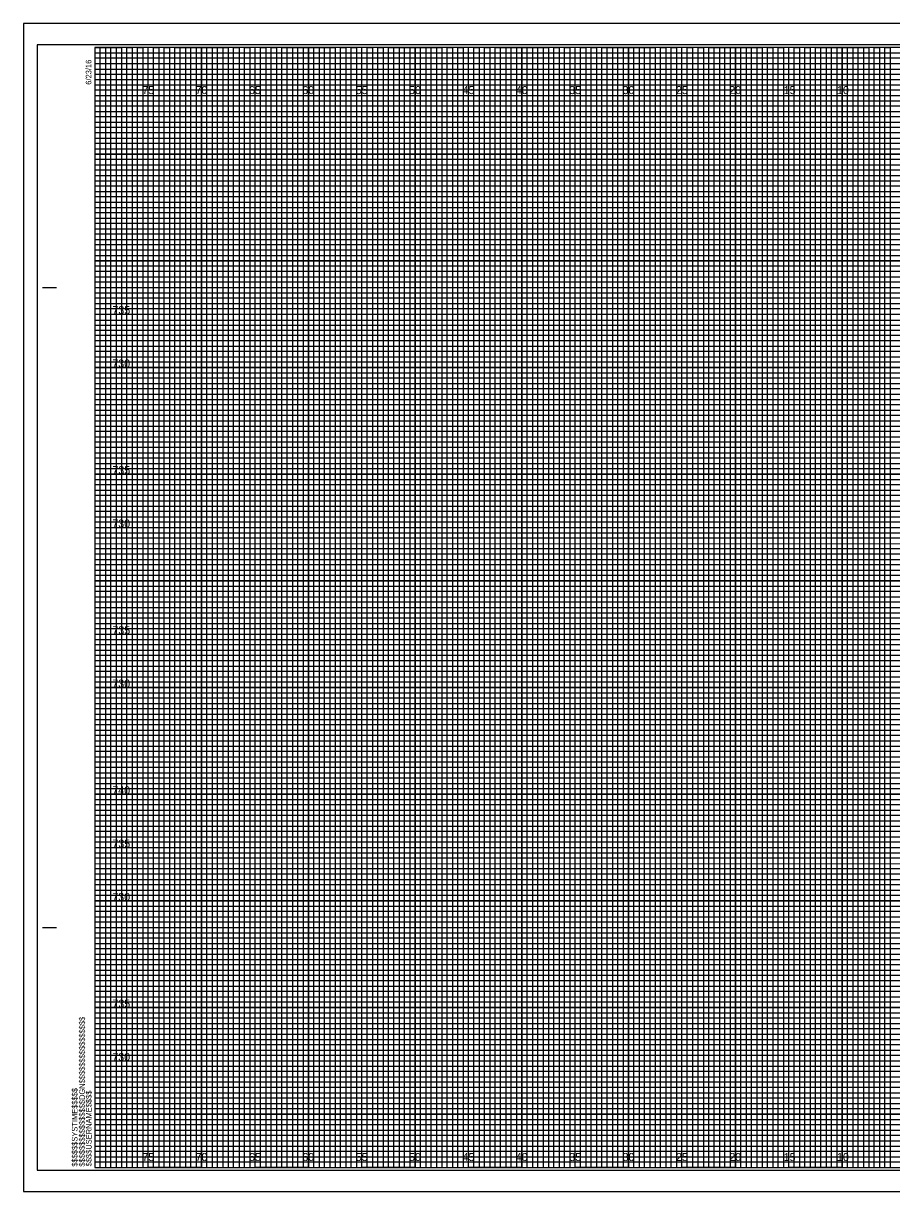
# Model space of a CAD drawing. Extents: x -7 to 162, y 108 to 217.
# Drawn here: x -6.7 to 74.6, y 107.7 to 217.2 of the extents above; entities that cross this region are included whole.
import ezdxf

# ---------------------------------------------------------------- set-up
doc = ezdxf.new("R2010")
doc.units = 0
for name, color, linetype in [('Exist Cross Section Cell', 7, 'Continuous'), ('Exist XS Center Line Elevation Label', 7, 'Continuous'), ('Exist XS Ground Line', 7, 'Continuous'), ('Prop CMT Pvmt Course 1', 7, 'Continuous'), ('Prop CMT Pvmt Course 2', 7, 'Continuous'), ('Prop CMT Pvmt Course 3', 7, 'Continuous'), ('Prop CMT Pvmt Surface', 7, 'Continuous'), ('Prop CMT Pvmt Surface Shoulder', 7, 'Continuous'), ('Prop CMT Shld Paved Course 1', 7, 'Continuous'), ('Prop CMT Shld Paved Course 2', 7, 'Continuous'), ('Prop CMT Shld Paved Course 3', 7, 'Continuous')]:
    doc.layers.add(name, color=color, linetype=linetype)

msp = doc.modelspace()

# ---------------------------------------------------------------- linework, layer by layer
at = {"layer": 'Exist XS Center Line Elevation Label'}
for points in [[(0, 215), (2.5, 215), (2.5, 110), (7.5, 110), (7.5, 215), (12.5, 215), (12.5, 110), (17.5, 110), (17.5, 215), (22.5, 215), (22.5, 110), (27.5, 110), (27.5, 215), (32.5, 215), (32.5, 110), (37.5, 110), (37.5, 215), (42.5, 215), (42.5, 110), (47.5, 110), (47.5, 215), (52.5, 215), (52.5, 110), (57.5, 110), (57.5, 215), (62.5, 215), (62.5, 110), (67.5, 110), (67.5, 215), (72.5, 215), (72.5, 110), (77.5, 110)], [(0, 212.5), (137.5, 212.5)], [(0, 202.5), (160, 202.5), (160, 207.5), (0, 207.5)], [(0, 192.5), (160, 192.5), (160, 197.5), (0, 197.5)], [(0, 182.5), (160, 182.5), (160, 187.5), (0, 187.5)], [(0, 172.5), (160, 172.5), (160, 177.5), (0, 177.5)], [(0, 162.5), (160, 162.5), (160, 167.5), (0, 167.5)], [(0, 152.5), (160, 152.5), (160, 157.5), (0, 157.5)], [(0, 142.5), (160, 142.5), (160, 147.5), (0, 147.5)], [(0, 132.5), (160, 132.5), (160, 137.5), (0, 137.5)], [(0, 122.5), (160, 122.5), (160, 127.5), (0, 127.5)], [(0, 112.5), (160, 112.5), (160, 117.5), (0, 117.5)]]:
    msp.add_lwpolyline(points, dxfattribs=at)
at = {"layer": 'Exist XS Ground Line'}
for p, q in [((5, 215), (0, 215)), ((5, 110), (5, 215)), ((15, 215), (10, 215)), ((10, 215), (10, 110)), ((15, 110), (15, 215)), ((25, 215), (20, 215)), ((20, 215), (20, 110)), ((25, 110), (25, 215)), ((35, 215), (30, 215)), ((30, 215), (30, 110)), ((35, 110), (35, 215)), ((45, 215), (40, 215)), ((40, 215), (40, 110)), ((45, 110), (45, 215)), ((55, 215), (50, 215)), ((50, 215), (50, 110)), ((55, 110), (55, 215)), ((65, 215), (60, 215)), ((60, 215), (60, 110)), ((65, 110), (65, 215)), ((75, 215), (70, 215)), ((70, 215), (70, 110)), ((10, 110), (5, 110)), ((20, 110), (15, 110)), ((30, 110), (25, 110)), ((40, 110), (35, 110)), ((50, 110), (45, 110)), ((60, 110), (55, 110)), ((70, 110), (65, 110))]:
    msp.add_line(p, q, dxfattribs=at)
for points in [[(0, 210), (160, 210), (160, 205), (0, 205)], [(0, 200), (160, 200), (160, 195), (0, 195)], [(0, 190), (160, 190), (160, 185), (0, 185)], [(0, 180), (160, 180), (160, 175), (0, 175)], [(0, 170), (160, 170), (160, 165), (0, 165)], [(0, 160), (160, 160), (160, 155), (0, 155)], [(0, 150), (160, 150), (160, 145), (0, 145)], [(0, 140), (160, 140), (160, 135), (0, 135)], [(0, 130), (160, 130), (160, 125), (0, 125)], [(0, 120), (160, 120), (160, 115), (0, 115)]]:
    msp.add_lwpolyline(points, dxfattribs=at)
at = {"layer": 'Prop CMT Pvmt Course 1'}
for p, q in [((5, 110), (5, 215)), ((10, 110), (10, 215)), ((15, 110), (15, 215)), ((20, 110), (20, 215)), ((25, 110), (25, 215)), ((30, 110), (30, 215)), ((35, 110), (35, 215)), ((40, 110), (40, 215)), ((45, 110), (45, 215)), ((50, 110), (50, 215)), ((55, 110), (55, 215)), ((60, 110), (60, 215)), ((65, 110), (65, 215)), ((70, 110), (70, 215)), ((0, 210), (160, 210)), ((0, 205), (160, 205)), ((0, 200), (160, 200)), ((0, 195), (160, 195)), ((0, 190), (160, 190)), ((0, 185), (160, 185)), ((0, 180), (160, 180)), ((0, 175), (160, 175)), ((0, 170), (160, 170)), ((0, 165), (160, 165)), ((0, 160), (160, 160)), ((0, 155), (160, 155)), ((0, 150), (160, 150)), ((0, 145), (160, 145)), ((0, 140), (160, 140)), ((0, 135), (160, 135)), ((0, 130), (160, 130)), ((0, 125), (160, 125)), ((0, 120), (160, 120)), ((0, 115), (160, 115))]:
    msp.add_line(p, q, dxfattribs=at)
at = {"layer": 'Prop CMT Pvmt Course 2'}
for p, q in [((161.65, 217.25), (-6.7, 217.25)), ((-6.7, 217.25), (-6.7, 107.75)), ((-6.7, 107.75), (161.65, 107.75))]:
    msp.add_line(p, q, dxfattribs=at)
at = {"layer": 'Prop CMT Pvmt Surface'}
msp.add_lwpolyline([(-6.7, 107.75), (161.65, 107.75), (161.65, 217.25), (-6.7, 217.25)], close=True, dxfattribs=at)
at = {"layer": 'Prop CMT Pvmt Surface Shoulder'}
msp.add_lwpolyline([(-5.4, 109.75), (161.2, 109.75), (161.2, 215.25), (-5.4, 215.25)], close=True, dxfattribs=at)
at = {"layer": 'Prop CMT Shld Paved Course 1'}
for p, q in [((0, 214.5), (130, 214.5)), ((130, 213.99), (0, 213.99)), ((0, 213.99), (0, 213.5)), ((0, 213.5), (130, 213.5)), ((130, 212.94), (0, 212.94)), ((0, 212.94), (0, 212)), ((0, 212), (160, 212))]:
    msp.add_line(p, q, dxfattribs=at)
for points in [[(0, 211.5), (135, 211.5), (160, 211.5), (160, 211), (0, 211)], [(0, 210.5), (160, 210.5), (160, 209.5), (0, 209.5)], [(0, 209), (160, 209), (160, 208.5), (0, 208.49)], [(0, 208), (160, 208), (160, 207), (0, 207)], [(0, 206.5), (160, 206.5), (160, 206), (0, 206)], [(0, 205.5), (160, 205.5), (160, 204.5), (0, 204.5)], [(0, 204), (160, 204), (160, 203.5), (0, 203.5)], [(0, 203), (160, 203), (160, 202), (0, 202)], [(0, 201.5), (160, 201.5), (160, 201), (0, 201)], [(0, 200.5), (160, 200.5), (160, 199.5), (0, 199.5)], [(0, 199), (160, 199), (160, 198.5), (0, 198.5)], [(0, 198), (160, 198), (160, 196.97), (160, 196.5), (160, 196), (0, 196)], [(0, 197), (160, 197), (160, 196.5), (0, 196.5)], [(0, 195.5), (160, 195.5), (160, 194.5), (0, 194.52)], [(0, 194.52), (160, 194.5), (160, 194), (0, 194)], [(0, 193.5), (160, 193.5), (160, 193), (0, 193)], [(0, 192), (160, 192), (160, 191.5), (0, 191.5)], [(0, 191), (160, 191), (160, 190.5), (0, 190.5)], [(-0.04, 189.44), (160, 189.44), (160, 188.94), (-0.04, 188.94)], [(0, 188.5), (160, 188.5), (160, 188), (0, 188)], [(0, 187), (160, 187), (160, 186.5), (0, 186.5)], [(0, 186), (160, 186), (160, 185.5), (0, 185.5)], [(0, 184.5), (160, 184.5), (160, 184), (0, 184)], [(0, 183.5), (160, 183.5), (160, 183), (0, 183)], [(0, 182), (160, 182), (160, 181.5), (0, 181.5)], [(0, 181), (160, 181), (160, 180.5), (0, 180.5)], [(0, 179.5), (160, 179.5), (160, 178.99), (0, 179)], [(0, 178.5), (160, 178.5), (160, 178), (0, 178)], [(0, 177), (160, 177), (160, 176.5), (0, 176.5)], [(0, 176), (160, 176), (160, 175.5), (0, 175.5)], [(0, 174.5), (160, 174.5), (160, 174), (0, 174)], [(0, 173.5), (160, 173.5), (160, 173), (0, 173)], [(0, 172), (160, 172), (160, 171.5), (0, 171.5)], [(0, 171), (160, 171), (160, 170.5), (0, 170.5)], [(0, 169.5), (160, 169.5), (160, 169), (0, 169)], [(0, 168.5), (160.03, 168.46), (160, 168), (0, 168)], [(0, 167), (160, 167), (160, 166.5), (0, 166.5)], [(0, 166), (160, 166), (160, 165.5), (0, 165.5)], [(0, 164.5), (160, 164.5), (160, 164), (0, 164)], [(0, 163.5), (160, 163.5), (160, 163), (0, 163)], [(0, 162), (160, 162), (160, 161.5), (0, 161.5)], [(0, 161), (160, 161), (160, 160.5), (0, 160.5)], [(0, 159.5), (160, 159.5), (160, 159), (0, 159)], [(0, 158.5), (160, 158.5), (160, 158), (0, 158)], [(0, 157), (160, 157), (160, 156.5), (0, 156.5)], [(0, 156), (160, 156), (160, 155.5), (0, 155.5)], [(0, 154.5), (160, 154.5), (160, 154), (0, 154)], [(0, 153.5), (160, 153.5), (160, 153), (0, 153)], [(0, 152), (160, 152), (160, 151.5), (0, 151.5)], [(0, 151), (160, 151), (160, 150.5), (0, 150.5)], [(0, 149.5), (160, 149.5), (160, 148.99), (0, 149)], [(0, 148.5), (160, 148.5), (160, 148), (0, 148)], [(0, 147), (160, 147), (160, 146.5), (0, 146.5)], [(0, 146), (160, 146), (160, 145.5), (0, 145.5)], [(0, 144.5), (160, 144.5), (160, 144), (0, 144)], [(0, 143.5), (160, 143.5), (160, 143), (0, 143)], [(0, 142), (160, 142), (160, 141.5), (0, 141.5)], [(0, 141), (160, 141), (160, 140.5), (0, 140.5)], [(0, 139.5), (160, 139.5), (160, 139), (0, 139)], [(0, 138.5), (160.03, 138.46), (160, 138), (0, 138)], [(0, 137), (160, 137), (160, 136.5), (0, 136.5)], [(0, 136), (160, 136), (160, 135.5), (0, 135.5)], [(0, 134.5), (160, 134.5), (160, 134), (0, 134)], [(0, 133.5), (160, 133.5), (160, 133), (0, 133)], [(0, 132), (160, 132), (160, 131.5), (0, 131.5)], [(0, 131), (160, 131), (160, 130.5), (0, 130.5)], [(0, 129.5), (160, 129.5), (160, 129), (0, 129)], [(0, 128.5), (160, 128.5), (160, 128), (0, 128)], [(0, 127), (160, 127), (160, 126.5), (0, 126.5)], [(0, 126), (160, 126), (160, 125.5), (0, 125.5)], [(0, 124.5), (160, 124.5), (160, 124), (0, 124)], [(0, 123.5), (160, 123.5), (160, 123), (0, 123)], [(0, 122), (160, 122), (160, 121.5), (0, 121.5)], [(0, 121), (160, 121), (160, 120.5), (0, 120.5)], [(0, 119.5), (160, 119.5), (160, 119), (0, 119)], [(0, 118.5), (160, 118.5), (160, 118), (0, 118)], [(0, 117), (160, 117), (160, 116.5), (0, 116.5)], [(0, 116), (160, 116), (160, 115.5), (0, 115.5)], [(0, 114.5), (160, 114.5), (160, 114), (0, 114)], [(0, 113.5), (160, 113.5), (160, 113), (0, 113)], [(0, 112), (160, 112), (160, 111.5), (0, 111.5)], [(0, 111), (160, 111), (160, 110.5), (0, 110.5)]]:
    msp.add_lwpolyline(points, dxfattribs=at)
at = {"layer": 'Prop CMT Shld Paved Course 2'}
for p, q in [((-4.9, 192.5), (-3.65, 192.5)), ((-4.85, 192.5), (-3.6, 192.5)), ((-4.9, 132.5), (-3.65, 132.5)), ((-4.85, 132.5), (-3.6, 132.5)), ((0, 110), (0, 110)), ((0, 110), (0, 110)), ((0, 110), (0, 110)), ((0, 110), (0, 110)), ((0, 110), (0, 110)), ((0, 110), (0, 110)), ((0, 110), (0, 110))]:
    msp.add_line(p, q, dxfattribs=at)
msp.add_lwpolyline([(160, 215), (0, 215), (0, 110), (160, 110)], close=True, dxfattribs=at)
at = {"layer": 'Prop CMT Shld Paved Course 3'}
for points in [[(0, 110), (0.5, 110), (0.5, 215), (1, 215), (1, 110)], [(1, 110), (1.5, 110), (1.5, 215), (2, 215), (2, 110)], [(2.5, 110), (3, 110), (3, 215), (3.5, 215), (3.5, 110)], [(3.5, 110), (4, 110), (4, 215), (4.5, 215), (4.5, 110)], [(5, 110), (5.5, 110), (5.5, 215), (6, 215), (6, 110)], [(6, 110), (6.5, 110), (6.5, 215), (7, 215), (7, 110)], [(7.5, 110), (8, 110), (8, 215), (8.5, 215), (8.5, 110)], [(8.5, 110), (9, 110), (9, 215), (9.5, 215), (9.5, 110)], [(10, 110), (10.5, 110), (10.5, 215), (11, 215), (11, 110)], [(11, 110), (11.5, 110), (11.5, 215), (12, 215), (12, 110)], [(12.5, 110), (13, 110), (13, 215), (13.5, 215), (13.5, 110)], [(13.5, 110), (14, 110), (14, 215), (14.5, 215), (14.5, 110)], [(15, 110), (15.5, 110), (15.5, 215), (16, 215), (16, 110)], [(16, 110), (16.5, 110), (16.5, 215), (17, 215), (17, 110)], [(17.5, 110), (18, 110), (18, 215), (18.5, 215), (18.5, 110)], [(18.5, 110), (19, 110), (19, 215), (19.5, 215), (19.5, 110)], [(20, 110), (20.5, 110), (20.5, 215), (21, 215), (21, 110)], [(21, 110), (21.5, 110), (21.5, 215), (22, 215), (22, 110)], [(22.5, 110), (23, 110), (23, 215), (23.5, 215), (23.5, 110)], [(23.5, 110), (24, 110), (24, 215), (24.5, 215), (24.5, 110)], [(25, 110), (25.5, 110), (25.5, 215), (26, 215), (26, 110)], [(26, 110), (26.5, 110), (26.5, 215), (27, 215), (27, 110)], [(27.5, 110), (28, 110), (28, 215), (28.5, 215), (28.5, 110)], [(28.5, 110), (29, 110), (29, 215), (29.5, 215), (29.5, 110)], [(30, 110), (30.5, 110), (30.5, 215), (31, 215), (31, 110)], [(31, 110), (31.5, 110), (31.5, 215), (32, 215), (32, 110)], [(32.5, 110), (33, 110), (33, 215), (33.5, 215), (33.5, 110)], [(33.5, 110), (34, 110), (34, 215), (34.5, 215), (34.5, 110)], [(35, 110), (35.5, 110), (35.5, 215), (36, 215), (36, 110)], [(36, 110), (36.5, 110), (36.5, 215), (37, 215), (37, 110)], [(37.5, 110), (38, 110), (38, 215), (38.5, 215), (38.5, 110)], [(38.5, 110), (39, 110), (39, 215), (39.5, 215), (39.5, 110)], [(40, 110), (40.5, 110), (40.5, 215), (41, 215), (41, 110)], [(41, 110), (41.5, 110), (41.5, 215), (42, 215), (42, 110)], [(42.5, 110), (43, 110), (43, 215), (43.5, 215), (43.5, 110)], [(43.5, 110), (44, 110), (44, 215), (44.5, 215), (44.5, 110)], [(45, 110), (45.5, 110), (45.5, 215), (46, 215), (46, 110)], [(46, 110), (46.5, 110), (46.5, 215), (47, 215), (47, 110)], [(47.5, 110), (48, 110), (48, 215), (48.5, 215), (48.5, 110)], [(48.5, 110), (49, 110), (49, 215), (49.5, 215), (49.5, 110)], [(50, 110), (50.5, 110), (50.5, 215), (51, 215), (51, 110)], [(51, 110), (51.5, 110), (51.5, 215), (52, 215), (52, 110)], [(52.5, 110), (53, 110), (53, 215), (53.5, 215), (53.5, 110)], [(53.5, 110), (54, 110), (54, 215), (54.5, 215), (54.5, 110)], [(55, 110), (55.5, 110), (55.5, 215), (56, 215), (56, 110)], [(56, 110), (56.5, 110), (56.5, 215), (57, 215), (57, 110)], [(57.5, 110), (58, 110), (58, 215), (58.5, 215), (58.5, 110)], [(58.5, 110), (59, 110), (59, 215), (59.5, 215), (59.5, 110)], [(60, 110), (60.5, 110), (60.5, 215), (61, 215), (61, 110)], [(61, 110), (61.5, 110), (61.5, 215), (62, 215), (62, 110)], [(62.5, 110), (63, 110), (63, 215), (63.5, 215), (63.5, 110)], [(63.5, 110), (64, 110), (64, 215), (64.5, 215), (64.5, 110)], [(65, 110), (65.5, 110), (65.5, 215), (66, 215), (66, 110)], [(66, 110), (66.5, 110), (66.5, 215), (67, 215), (67, 110)], [(67.5, 110), (68, 110), (68, 215), (68.5, 215), (68.5, 110)], [(68.5, 110), (69, 110), (69, 215), (69.5, 215), (69.5, 110)], [(70, 110), (70.5, 110), (70.5, 215), (71, 215), (71, 110)], [(71, 110), (71.5, 110), (71.5, 215), (72, 215), (72, 110)], [(72.5, 110), (73, 110), (73, 215), (73.5, 215), (73.5, 110)], [(73.5, 110), (74, 110), (74, 215), (74.5, 215), (74.5, 110)]]:
    msp.add_lwpolyline(points, dxfattribs=at)

# ---------------------------------------------------------------- texts
at = {"layer": 'Exist Cross Section Cell'}
for s, p in [('75', (4.44, 210.62)), ('70', (9.43, 210.62)), ('65', (14.44, 210.62)), ('60', (19.43, 210.62)), ('55', (24.44, 210.62)), ('50', (29.43, 210.62)), ('45', (34.44, 210.62)), ('40', (39.43, 210.62)), ('35', (44.44, 210.62)), ('30', (49.43, 210.62)), ('25', (54.44, 210.62)), ('20', (59.43, 210.62)), ('15', (64.53, 210.62)), ('10', (69.52, 210.62)), ('75', (4.44, 110.62)), ('70', (9.43, 110.62)), ('65', (14.44, 110.62)), ('60', (19.43, 110.62)), ('55', (24.44, 110.62)), ('50', (29.43, 110.62)), ('45', (34.44, 110.62)), ('40', (39.43, 110.62)), ('35', (44.44, 110.62)), ('30', (49.43, 110.62)), ('25', (54.44, 110.62)), ('20', (59.43, 110.62)), ('15', (64.53, 110.62)), ('10', (69.52, 110.62))]:
    msp.add_text(s, height=0.75, dxfattribs=at).set_placement(p)
at = {"layer": 'Prop CMT Pvmt Course 3'}
for s, p in [('735', (1.64, 190)), ('730', (1.63, 185)), ('735', (1.64, 175)), ('730', (1.63, 170)), ('735', (1.64, 160)), ('730', (1.63, 155)), ('740', (1.63, 145)), ('735', (1.64, 140)), ('730', (1.63, 135)), ('735', (1.64, 125)), ('730', (1.63, 120))]:
    msp.add_text(s, height=0.75, dxfattribs=at).set_placement(p)
at = {"layer": 'Prop CMT Shld Paved Course 2'}
for s, p in [('6/23/16', (-0.33, 211.5)), ('$$$$$$$$$$$$$$$$DGN$$$$$$$$$$$$$$$$', (-0.94, 110.09)), ('$$$$$$SYSTIME$$$$$', (-1.63, 110.09)), ('$$$$USERNAME$$$$', (-0.31, 110.12))]:
    msp.add_text(s, height=0.525, rotation=90, dxfattribs=at).set_placement(p)

doc.saveas('drawing.dxf')
